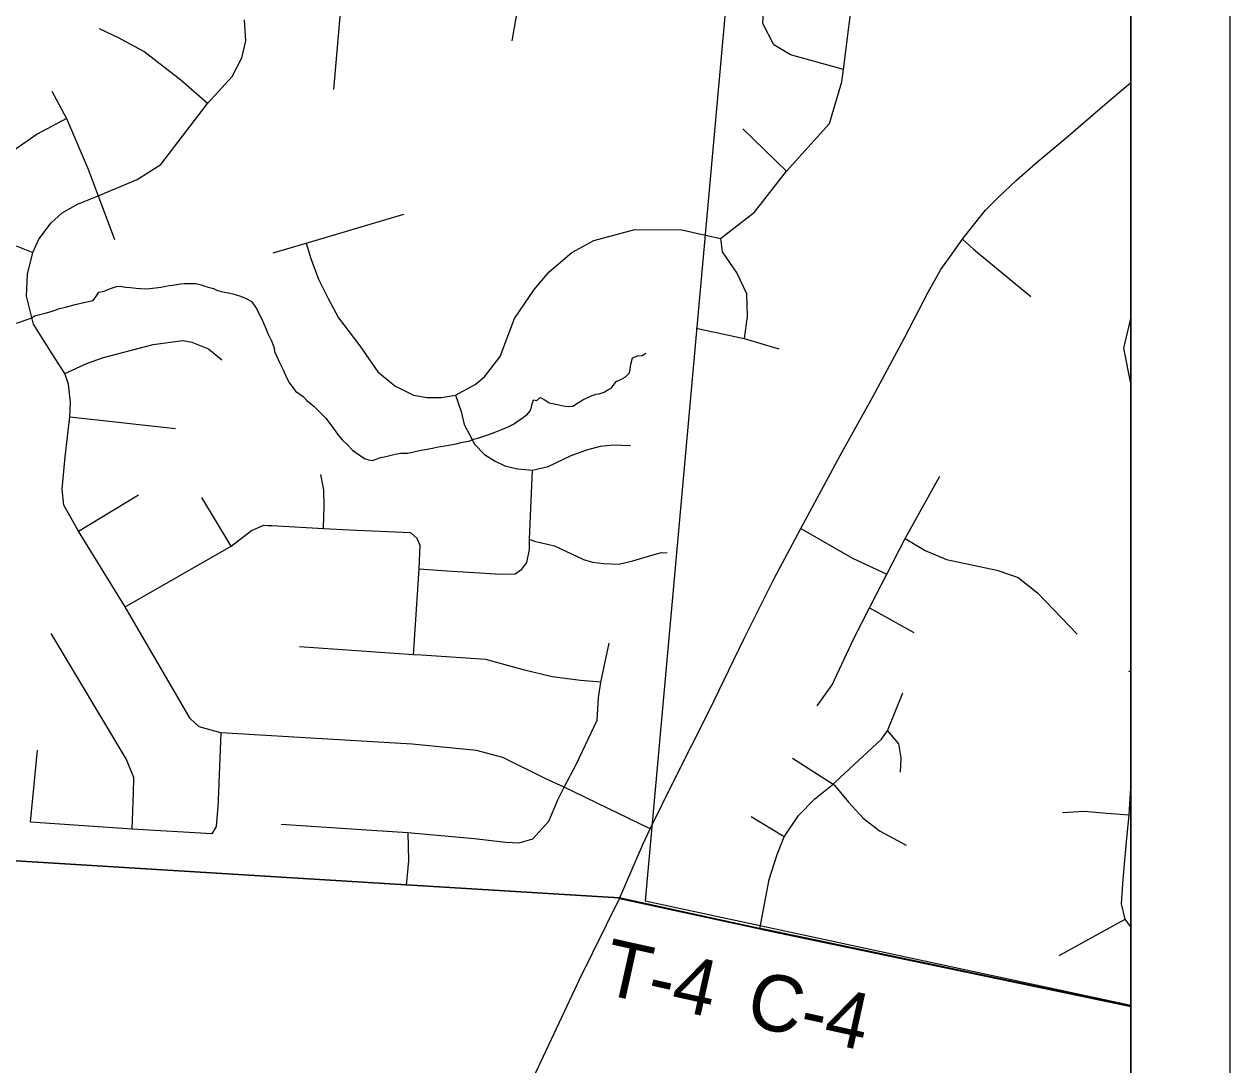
# Model space of a CAD drawing. Extents: x 0 to 34, y 0 to 22.
# Drawn here: x 7.782 to 9, y 14.8 to 15.851 of the extents above; entities that cross this region are included whole.
import ezdxf

# ---------------------------------------------------------------- set-up
doc = ezdxf.new("R2010")
doc.units = 0
for name, color, linetype in [('Default', 7, 'Continuous'), ('GM_X_County_Road', 7, 'Continuous'), ('GM_X_County_Road_Text', 7, 'Continuous'), ('GM_X_Minor_River', 7, 'Continuous'), ('GM_X_Township_Road', 7, 'Continuous'), ('GM_X_Township_Road_Text', 7, 'Continuous'), ('GM_X_US_Route', 7, 'Continuous'), ('SH_Cut_Line', 7, 'Continuous'), ('SH_Data', 7, 'Continuous')]:
    doc.layers.add(name, color=color, linetype=linetype)

msp = doc.modelspace()

# ---------------------------------------------------------------- linework, layer by layer
at = {"layer": 'Default'}
msp.add_lwpolyline([(8.9, 14.8605), (8.9, 15.9093), (8.5037, 16.0129), (8.4096, 14.9658)], close=True, dxfattribs=at)
at = {"layer": 'GM_X_County_Road'}
msp.add_lwpolyline([(8.3835, 14.9683), (8.5253, 14.9375), (8.5295, 14.9366), (8.9, 14.859)], dxfattribs=at)
at = {"layer": 'GM_X_Minor_River'}
for points in [[(7.7748, 15.5491), (7.7894, 15.5543), (7.7929, 15.5565), (7.8036, 15.5592), (7.8098, 15.5609), (7.8136, 15.5623), (7.8182, 15.5641), (7.824, 15.5654), (7.8339, 15.5682), (7.8427, 15.5702), (7.8519, 15.5722), (7.8555, 15.577), (7.8579, 15.5804), (7.8628, 15.5817), (7.8705, 15.5846), (7.8755, 15.5863), (7.8793, 15.5866), (7.8846, 15.5856), (7.8899, 15.5851), (7.8956, 15.5845), (7.9043, 15.5839), (7.9093, 15.5841), (7.9203, 15.5857), (7.9253, 15.5867), (7.9291, 15.5873), (7.9345, 15.5879), (7.9402, 15.5889), (7.944, 15.5892), (7.9482, 15.5894), (7.952, 15.5893), (7.9558, 15.5892), (7.9611, 15.5879), (7.9648, 15.5866), (7.9697, 15.5853), (7.9735, 15.5841), (7.9776, 15.5824), (7.9844, 15.5807), (7.9886, 15.5798), (7.9943, 15.5785), (8.001, 15.5764), (8.0074, 15.5739), (8.0119, 15.5711), (8.017, 15.5641), (8.0195, 15.5591), (8.022, 15.5541), (8.0256, 15.5456), (8.0284, 15.5387), (8.032, 15.5313), (8.0349, 15.5244), (8.0351, 15.5206), (8.0405, 15.509), (8.0441, 15.5021), (8.0473, 15.4944), (8.0502, 15.4886), (8.0542, 15.4839), (8.0564, 15.4804), (8.0642, 15.4752), (8.0679, 15.4713), (8.072, 15.4678), (8.0753, 15.465)], [(8.0753, 15.465), (8.0816, 15.4587), (8.0871, 15.4532), (8.0897, 15.4497), (8.0941, 15.4439), (8.0963, 15.4404), (8.0999, 15.4357), (8.1036, 15.4314), (8.1088, 15.4263), (8.1139, 15.4209), (8.1206, 15.4161), (8.1262, 15.4125), (8.13, 15.4113), (8.1342, 15.4107), (8.1388, 15.4121), (8.1422, 15.4135), (8.1476, 15.4145), (8.1572, 15.4169), (8.1629, 15.4178), (8.1697, 15.418), (8.1759, 15.4194), (8.1831, 15.421), (8.1892, 15.422), (8.1946, 15.423), (8.2003, 15.4243), (8.2053, 15.4249), (8.2091, 15.4256), (8.2133, 15.4262), (8.2187, 15.4275), (8.2252, 15.4289), (8.2313, 15.4302), (8.2363, 15.432), (8.2405, 15.433), (8.2505, 15.4365), (8.257, 15.4389), (8.2639, 15.4414), (8.2712, 15.4446), (8.2766, 15.4471), (8.2867, 15.4544), (8.2906, 15.4573), (8.2934, 15.4606), (8.2946, 15.4644), (8.2955, 15.4678), (8.2967, 15.4719), (8.3001, 15.4711), (8.3036, 15.474), (8.3074, 15.472), (8.3126, 15.4688), (8.3209, 15.467), (8.3266, 15.4657), (8.3319, 15.4651), (8.3365, 15.4654), (8.3423, 15.469), (8.3465, 15.4719), (8.3542, 15.4755), (8.3596, 15.4776), (8.363, 15.4779), (8.368, 15.4796), (8.3719, 15.4818), (8.3754, 15.484), (8.3801, 15.4903), (8.3848, 15.4924), (8.3898, 15.4949), (8.3937, 15.499), (8.3942, 15.5024), (8.3951, 15.5077), (8.3968, 15.5141), (8.4022, 15.5162), (8.4064, 15.5165), (8.4102, 15.519)]]:
    msp.add_lwpolyline(points, dxfattribs=at)
at = {"layer": 'GM_X_Township_Road'}
for p, q in [((8.5521, 15.7026), (8.508, 15.7454)), ((7.8286, 15.4545), (7.9352, 15.4429)), ((7.8374, 15.3392), (7.898, 15.3757)), ((7.9914, 15.3241), (7.9618, 15.3732)), ((8.6359, 15.2616), (8.6809, 15.2369)), ((8.9, 15.1966), (8.8981, 15.1976)), ((8.5498, 15.0305), (8.5164, 15.0507)), ((8.8276, 14.9105), (8.8942, 14.9474))]:
    msp.add_line(p, q, dxfattribs=at)
for points in [[(5.9659, 15.1626), (6.3032, 15.1064), (6.401, 15.0917), (6.488, 15.0839), (6.9119, 15.0636), (7.3636, 15.0306), (7.437, 15.0262), (7.6301, 15.0148), (7.6752, 15.0122), (8.168, 14.9819), (8.3833, 14.9688), (8.525, 14.938), (8.5293, 14.9371), (8.9, 14.8595), (8.9, 19.9667)], [(8.1128, 16.0269), (8.1076, 15.9389), (8.1015, 15.8627), (8.0946, 15.7854)], [(8.6097, 15.8056), (8.5563, 15.8204), (8.5395, 15.8302), (8.5283, 15.8519), (8.5304, 15.8848), (8.5332, 15.9304), (8.5339, 15.9851), (8.5358, 15.9947)], [(8.2979, 15.914), (8.281, 15.8692), (8.2748, 15.8343)], [(8.4569, 15.6412), (8.4855, 15.6346), (8.5199, 15.6613), (8.5521, 15.7026), (8.5956, 15.751), (8.6082, 15.793), (8.6097, 15.8056), (8.6208, 15.894)], [(8.4146, 15.0386), (8.3276, 15.0805), (8.3092, 15.0891), (8.2658, 15.1105), (8.2391, 15.1177), (8.1742, 15.124), (7.9811, 15.1355), (7.959, 15.1414), (7.9499, 15.1499), (7.8843, 15.2628), (7.8374, 15.3392), (7.8223, 15.3655), (7.8209, 15.3816), (7.8237, 15.4142), (7.8286, 15.4545), (7.8293, 15.4692), (7.8272, 15.4875), (7.8234, 15.4984), (7.8107, 15.5183), (7.7918, 15.5481), (7.7848, 15.5765), (7.7859, 15.5989), (7.7911, 15.6207), (7.7971, 15.634), (7.8097, 15.6505), (7.8209, 15.6606), (7.8363, 15.6693), (7.8549, 15.677), (7.857, 15.6779), (7.8966, 15.6942), (7.9204, 15.7096), (7.9674, 15.771), (7.9926, 15.7983), (8.0021, 15.8173), (8.0063, 15.8344), (8.0049, 15.8555)], [(7.9674, 15.771), (7.9406, 15.7946), (7.9031, 15.8237), (7.8778, 15.8373), (7.8583, 15.8466)], [(7.8102, 15.7834), (7.8252, 15.7559), (7.8471, 15.7047), (7.857, 15.6779), (7.8735, 15.6336)], [(7.8252, 15.7559), (7.7954, 15.74), (7.7709, 15.723), (7.7467, 15.6967)], [(8.0338, 15.6202), (8.067, 15.6301), (8.1657, 15.6595)], [(8.067, 15.6301), (8.0718, 15.6147), (8.0795, 15.5936), (8.0893, 15.574), (8.0998, 15.5547), (8.1215, 15.5263), (8.1394, 15.5001), (8.1566, 15.486), (8.1756, 15.4766), (8.1892, 15.4743), (8.2038, 15.4742), (8.2179, 15.4765), (8.2378, 15.4874), (8.2472, 15.4952), (8.2631, 15.5155), (8.2774, 15.554), (8.2978, 15.5835), (8.3125, 15.601), (8.3356, 15.6206), (8.3577, 15.6329), (8.399, 15.6437), (8.4464, 15.6436), (8.4569, 15.6412)], [(7.5023, 15.5369), (7.5072, 15.5912), (7.614, 15.5691), (7.6323, 15.5688), (7.6501, 15.574), (7.6747, 15.5891), (7.7037, 15.6028), (7.7405, 15.6217), (7.7545, 15.628), (7.7669, 15.6294), (7.7761, 15.6266), (7.7911, 15.6207)], [(8.4855, 15.6346), (8.4873, 15.6213), (8.502, 15.5999), (8.5118, 15.5793), (8.5125, 15.5561), (8.5094, 15.5337)], [(8.7299, 15.6341), (8.741, 15.6241), (8.799, 15.5761)], [(8.9, 15.5543), (8.8998, 15.554), (8.8925, 15.5239), (8.9, 15.4865)], [(8.461, 15.5442), (8.5094, 15.5337), (8.5444, 15.5232)], [(7.8234, 15.4984), (7.8462, 15.5089), (7.8625, 15.5144), (7.9127, 15.5278), (7.9425, 15.5316), (7.9516, 15.53), (7.9684, 15.5232), (7.9821, 15.5123)], [(8.2179, 15.4765), (8.2236, 15.46), (8.2267, 15.4469), (8.2317, 15.4373), (8.2373, 15.4269), (8.2474, 15.4166), (8.258, 15.4099), (8.2677, 15.4051), (8.2807, 15.4021), (8.2958, 15.4009), (8.3116, 15.4044), (8.3347, 15.4155), (8.3505, 15.4214), (8.3645, 15.4249), (8.3773, 15.4265), (8.3947, 15.4258)], [(8.0848, 15.342), (8.0851, 15.3542), (8.0855, 15.3636), (8.0851, 15.3808), (8.0821, 15.3965)], [(8.1812, 15.3012), (8.2092, 15.299), (8.2478, 15.2969), (8.2635, 15.2957), (8.2781, 15.2962), (8.2851, 15.3007), (8.2899, 15.3075), (8.2926, 15.3206), (8.2928, 15.3311), (8.2958, 15.4009)], [(8.5831, 15.1626), (8.5985, 15.184), (8.6202, 15.2309), (8.6359, 15.2616), (8.6371, 15.2639), (8.6535, 15.2958), (8.6721, 15.3319), (8.7071, 15.3946)], [(7.8843, 15.2628), (7.9914, 15.3241), (8.012, 15.3398), (8.0245, 15.3452), (8.0286, 15.345), (8.0326, 15.3448)], [(8.0326, 15.3448), (8.0848, 15.342), (8.1107, 15.3405), (8.1726, 15.3377)], [(8.1754, 15.2144), (8.1812, 15.3012), (8.1822, 15.3247), (8.1793, 15.3318), (8.1726, 15.3377)], [(8.2928, 15.3311), (8.2974, 15.3292), (8.3121, 15.3256), (8.318, 15.3242), (8.3471, 15.3106), (8.3564, 15.3077), (8.3678, 15.3064), (8.3829, 15.3059), (8.397, 15.3093), (8.4185, 15.3155), (8.426, 15.3176), (8.4318, 15.3173)], [(8.5668, 15.3419), (8.6188, 15.3119), (8.6535, 15.2958)], [(8.6721, 15.3319), (8.6924, 15.3196), (8.7138, 15.3105), (8.7647, 15.2996), (8.7677, 15.2989), (8.7863, 15.2923), (8.8056, 15.2768), (8.8459, 15.2351)], [(7.8913, 15.0381), (7.8929, 15.0749), (7.8932, 15.0905), (7.8854, 15.1092), (7.8097, 15.2358)], [(8.3649, 15.1866), (8.3441, 15.1883), (8.3155, 15.1921), (8.2878, 15.1987), (8.2485, 15.2096), (8.1837, 15.2138), (8.1754, 15.2144), (8.0605, 15.2222)], [(8.3276, 15.0805), (8.3402, 15.1042), (8.3611, 15.1481), (8.3624, 15.1707), (8.3649, 15.1866), (8.3656, 15.1913), (8.373, 15.226)], [(8.5253, 14.9375), (8.5348, 14.9874), (8.5428, 15.0126), (8.5498, 15.0305), (8.5642, 15.0519), (8.581, 15.0687), (8.5992, 15.0837), (8.6013, 15.0855), (8.6483, 15.129), (8.6542, 15.1374), (8.6696, 15.1759)], [(5.2869, 14.1), (8.9, 14.1), (8.9, 14.8595), (8.5293, 14.9371), (8.525, 14.938), (8.3833, 14.9688), (8.168, 14.9819), (7.6752, 15.0122), (7.6301, 15.0148), (7.437, 15.0262), (7.3636, 15.0306), (6.9119, 15.0636), (6.488, 15.0839), (6.401, 15.0917), (6.3032, 15.1064), (5.9659, 15.1626)], [(8.6542, 15.1374), (8.6653, 15.1244), (8.6678, 15.1102), (8.6669, 15.0958)], [(7.9811, 15.1355), (7.9779, 15.0594), (7.9777, 15.0575)], [(7.9777, 15.0575), (7.9762, 15.0409), (7.972, 15.0335), (7.8913, 15.0381), (7.7887, 15.0451), (7.796, 15.118)], [(8.5582, 15.11), (8.5992, 15.0837), (8.6003, 15.0831), (8.615, 15.0655), (8.6297, 15.0494), (8.6462, 15.0364), (8.6731, 15.0221)], [(8.0419, 15.0431), (8.1232, 15.0377), (8.1699, 15.0348), (8.2368, 15.0289), (8.2689, 15.025), (8.2824, 15.0245), (8.296, 15.0285), (8.3122, 15.0462), (8.3213, 15.0679), (8.3276, 15.0805)], [(8.9, 14.9395), (8.8942, 14.9474), (8.8907, 14.9629), (8.8921, 14.9877), (8.896, 15.0291), (8.8984, 15.0522), (8.9, 15.0799)], [(8.8984, 15.0522), (8.8755, 15.0541), (8.8528, 15.0561), (8.8308, 15.0547)], [(8.1699, 15.0348), (8.1704, 15.0061), (8.1682, 14.9814)], [(8.3835, 14.9683), (8.5253, 14.9375), (8.5295, 14.9366), (8.9, 14.859)]]:
    msp.add_lwpolyline(points, dxfattribs=at)
at = {"layer": 'GM_X_US_Route'}
for points in [[(8.3835, 14.9683), (8.4071, 15.0226), (8.4146, 15.0386), (8.4396, 15.089), (8.4743, 15.1578), (8.5091, 15.23), (8.5397, 15.2915), (8.5668, 15.3419), (8.6064, 15.4157), (8.6394, 15.4748), (8.6713, 15.5345), (8.6954, 15.5804), (8.7082, 15.6036), (8.7169, 15.6154), (8.7299, 15.6341), (8.7398, 15.6465), (8.7533, 15.6633), (8.7662, 15.6764), (8.7841, 15.6935), (8.8041, 15.7107), (8.8347, 15.7364), (8.8712, 15.768), (8.9, 15.7923)], [(8.3384, 14.8761), (8.3432, 14.8862), (8.3835, 14.9683)], [(8.2958, 14.7837), (8.2992, 14.7923), (8.3384, 14.8761)]]:
    msp.add_lwpolyline(points, dxfattribs=at)
at = {"layer": 'SH_Cut_Line'}
for points in [[(5.9659, 15.1626), (6.3032, 15.1064), (6.401, 15.0917), (6.488, 15.0839), (6.9119, 15.0636), (7.3636, 15.0306), (7.437, 15.0262), (7.6301, 15.0148), (7.6752, 15.0122), (8.168, 14.9819), (8.3833, 14.9688), (8.525, 14.938), (8.5293, 14.9371), (8.9, 14.8595), (8.9, 20.9)], [(2.1, 14.1), (8.9, 14.1), (8.9, 14.8595), (8.5293, 14.9371), (8.525, 14.938), (8.3833, 14.9688), (8.168, 14.9819), (7.6752, 15.0122), (7.6301, 15.0148), (7.437, 15.0262), (7.3636, 15.0306), (6.9119, 15.0636), (6.488, 15.0839), (6.401, 15.0917), (6.3032, 15.1064), (5.9659, 15.1626)]]:
    msp.add_lwpolyline(points, dxfattribs=at)
at = {"layer": 'SH_Data'}
for p, q in [((9, 21), (9, 14)), ((8.9, 20.9), (8.9, 14.1))]:
    msp.add_line(p, q, dxfattribs=at)

# ---------------------------------------------------------------- texts
at = {"layer": 'GM_X_County_Road_Text'}
msp.add_text('C-4', height=0.05682, rotation=347.6074, dxfattribs=at).set_placement((8.5093, 14.8407))
at = {"layer": 'GM_X_Township_Road_Text'}
msp.add_text('T-4', height=0.05682, rotation=347.4717, dxfattribs=at).set_placement((8.3636, 14.8726))

doc.saveas('drawing.dxf')
